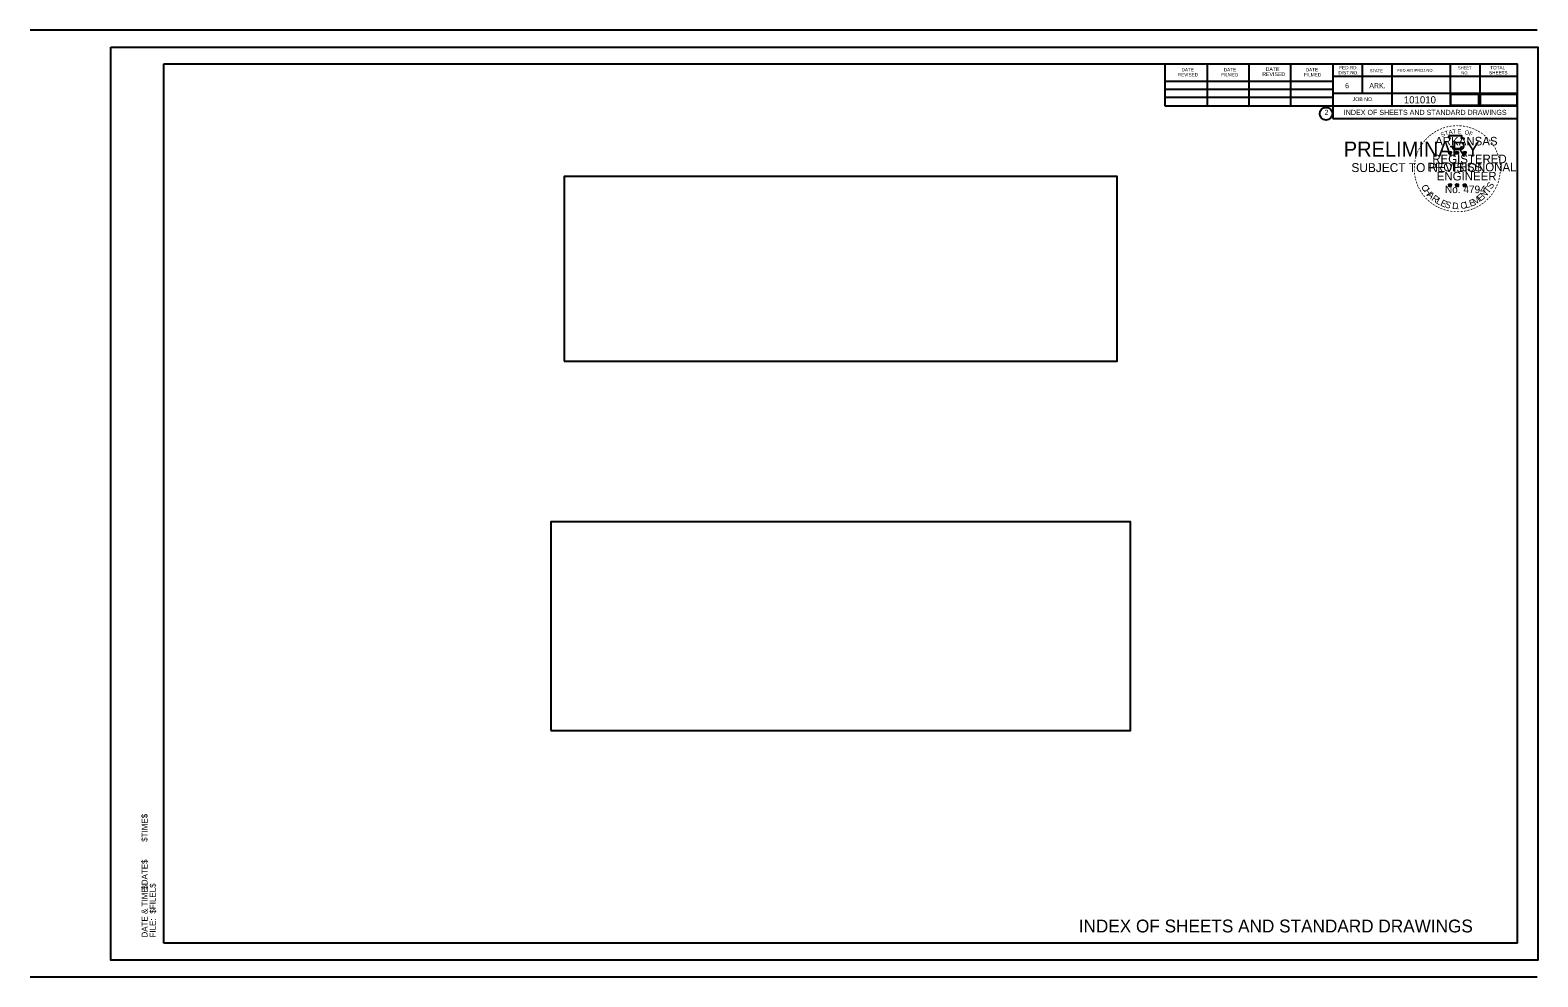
# Model space of a CAD drawing. Extents: x 3953 to 7490, y 10000 to 12548.
# Drawn here: x 3953 to 5714, y 10000 to 11106 of the extents above; entities that cross this region are included whole.
import ezdxf

# ---------------------------------------------------------------- set-up
doc = ezdxf.new("R2010")
doc.units = 0
for name, color, linetype in [('Default', 7, 'Continuous'), ('R_NoPlot', 7, 'Continuous'), ('STAMP_PE_FOSTER-SIGNATURE', 7, 'Continuous'), ('STAMP_PE_SEAL-INFO', 7, 'Continuous'), ('STAMP_PE_TAEGTMEYER', 7, 'Continuous'), ('STAMP_PRELIMINARY', 7, 'Continuous'), ('Total_Pages', 7, 'Continuous')]:
    doc.layers.add(name, color=color, linetype=linetype)

msp = doc.modelspace()

# ---------------------------------------------------------------- linework, layer by layer
at = {"layer": 'Default'}
for points in [[(5612.1, 11018.4), (5645.4, 11018.4), (5645.4, 11030.9), (5612.1, 11030.9)], [(4577.1, 10719.4), (5222.9, 10719.4), (5222.9, 10935.1), (4577.1, 10935.1)], [(4561.7, 10288), (5238.3, 10288), (5238.3, 10531.8), (4561.7, 10531.8)]]:
    msp.add_lwpolyline(points, close=True, dxfattribs=at)
at = {"layer": 'R_NoPlot'}
msp.add_lwpolyline([(4047.5, 11086.2), (5714.2, 11086.2), (5714.2, 10019.5), (4047.5, 10019.5)], close=True, dxfattribs=at)
at = {"layer": 'STAMP_PE_FOSTER-SIGNATURE'}
for p, q in [((5609.8, 10963.4), (5611.6, 10962.9)), ((5609.8, 10963.4), (5611.1, 10963.2)), ((5609.8, 10963.4), (5611, 10962.8)), ((5610.5, 10961.4), (5611.6, 10962.9)), ((5610.5, 10961.4), (5611.1, 10962.6)), ((5610.5, 10961.4), (5611.6, 10962.5)), ((5611.6, 10964.7), (5611.4, 10963.5)), ((5611.6, 10962.9), (5611.6, 10964.7)), ((5611.6, 10964.7), (5611.8, 10963.5)), ((5613.3, 10963.4), (5611.6, 10962.9)), ((5612.6, 10961.4), (5611.6, 10962.9)), ((5612.6, 10961.4), (5611.6, 10962.5)), ((5613.3, 10963.4), (5611.9, 10963.2)), ((5612.6, 10961.4), (5612, 10962.9)), ((5613.3, 10963.4), (5612.3, 10962.9)), ((5618.2, 10963.4), (5619.9, 10962.9)), ((5618.2, 10963.4), (5619.5, 10963.2)), ((5618.2, 10963.4), (5619.4, 10962.8)), ((5618.9, 10961.4), (5619.9, 10962.9)), ((5618.9, 10961.4), (5619.5, 10962.6)), ((5618.9, 10961.4), (5619.9, 10962.5)), ((5619.9, 10964.7), (5619.7, 10963.5)), ((5619.9, 10962.9), (5619.9, 10964.7)), ((5619.9, 10964.7), (5620.2, 10963.5)), ((5621.7, 10963.4), (5619.9, 10962.9)), ((5621, 10961.4), (5619.9, 10962.9)), ((5621, 10961.4), (5619.9, 10962.5)), ((5621.7, 10963.4), (5620.2, 10963.2)), ((5621, 10961.4), (5620.3, 10962.9)), ((5621.7, 10963.4), (5620.6, 10962.9)), ((5627, 10963.4), (5628.8, 10962.8)), ((5627, 10963.4), (5628.3, 10963.2)), ((5627, 10963.4), (5628.2, 10962.8)), ((5627.7, 10961.3), (5628.8, 10962.8)), ((5627.7, 10961.3), (5628.3, 10962.6)), ((5627.7, 10961.3), (5628.7, 10962.4)), ((5628.8, 10964.7), (5628.5, 10963.4)), ((5629.8, 10961.3), (5628.7, 10962.4)), ((5628.8, 10962.8), (5628.8, 10964.7)), ((5628.8, 10964.7), (5629, 10963.4)), ((5630.5, 10963.4), (5628.8, 10962.8)), ((5629.8, 10961.3), (5628.8, 10962.8)), ((5630.5, 10963.4), (5629.1, 10963.1)), ((5629.8, 10961.3), (5629.1, 10962.8)), ((5630.5, 10963.4), (5629.5, 10962.9)), ((5609.8, 10925.6), (5611.6, 10925)), ((5609.8, 10925.6), (5611.1, 10925.4)), ((5609.8, 10925.6), (5611, 10925)), ((5610.5, 10923.5), (5611.6, 10925)), ((5610.5, 10923.5), (5611.1, 10924.8)), ((5610.5, 10923.5), (5611.6, 10924.6)), ((5611.6, 10926.8), (5611.4, 10925.6)), ((5611.6, 10925), (5611.6, 10926.8)), ((5611.6, 10926.8), (5611.8, 10925.6)), ((5613.3, 10925.6), (5611.6, 10925)), ((5612.6, 10923.5), (5611.6, 10925)), ((5612.6, 10923.5), (5611.6, 10924.6)), ((5613.3, 10925.6), (5611.9, 10925.3)), ((5612.6, 10923.5), (5611.9, 10925)), ((5613.3, 10925.6), (5612.3, 10925.1)), ((5618.2, 10925.6), (5619.9, 10925)), ((5618.2, 10925.6), (5619.4, 10925.4)), ((5618.2, 10925.6), (5619.3, 10925)), ((5618.8, 10923.5), (5619.9, 10925)), ((5618.8, 10923.5), (5619.5, 10924.8)), ((5618.8, 10923.5), (5619.9, 10924.6)), ((5619.9, 10926.8), (5619.7, 10925.6)), ((5619.9, 10925), (5619.9, 10926.8)), ((5619.9, 10926.8), (5620.2, 10925.6)), ((5621.6, 10925.6), (5619.9, 10925)), ((5621, 10923.5), (5619.9, 10925)), ((5621, 10923.5), (5619.9, 10924.6)), ((5621.6, 10925.6), (5620.2, 10925.3)), ((5621, 10923.5), (5620.3, 10925)), ((5621.6, 10925.6), (5620.6, 10925.1)), ((5627, 10925.5), (5628.7, 10925)), ((5627, 10925.5), (5628.3, 10925.3)), ((5627, 10925.5), (5628.2, 10924.9)), ((5627.7, 10923.5), (5628.7, 10925)), ((5627.7, 10923.5), (5628.3, 10924.7)), ((5627.7, 10923.5), (5628.7, 10924.6)), ((5628.7, 10926.8), (5628.5, 10925.5)), ((5628.7, 10925), (5628.7, 10926.8)), ((5628.7, 10926.8), (5629, 10925.5)), ((5630.5, 10925.5), (5628.7, 10925)), ((5629.8, 10923.5), (5628.7, 10925)), ((5629.8, 10923.5), (5628.7, 10924.6)), ((5630.5, 10925.5), (5629, 10925.3)), ((5629.8, 10923.5), (5629.1, 10924.9)), ((5630.5, 10925.5), (5629.5, 10925))]:
    msp.add_line(p, q, dxfattribs=at)
for points in [[(5610, 10982.8), (5611.4, 10978.7)], [(5627.6, 10978.2), (5628.3, 10979.6), (5624.9, 10979.5), (5625.6, 10982.8), (5610, 10982.8)], [(5612.5, 10970.7), (5612.5, 10970.3), (5615.3, 10970.2), (5615, 10967.8), (5624.4, 10967.8), (5625.4, 10970.5)], [(5611.6, 10964.7), (5612.6, 10961.4), (5609.8, 10963.4), (5613.3, 10963.4), (5610.5, 10961.4), (5611.6, 10964.7)], [(5619.9, 10964.7), (5621, 10961.4), (5618.2, 10963.4), (5621.7, 10963.4), (5618.9, 10961.4), (5619.9, 10964.7)], [(5628.8, 10964.7), (5629.8, 10961.3), (5627, 10963.4), (5630.5, 10963.4), (5627.7, 10961.3), (5628.8, 10964.7)], [(5611.6, 10926.8), (5612.6, 10923.5), (5609.8, 10925.6), (5613.3, 10925.6), (5610.5, 10923.5), (5611.6, 10926.8)], [(5619.9, 10926.8), (5621, 10923.5), (5618.2, 10925.6), (5621.6, 10925.6), (5618.8, 10923.5), (5619.9, 10926.8)], [(5628.7, 10926.8), (5629.8, 10923.5), (5627, 10925.5), (5630.5, 10925.5), (5627.7, 10923.5), (5628.7, 10926.8)]]:
    msp.add_lwpolyline(points, dxfattribs=at)
for centre, radius in [((5611.6, 10962.9), 0.861), ((5611.6, 10962.9), 0.723), ((5611.6, 10962.9), 0.579), ((5611.6, 10962.9), 0.495), ((5611.6, 10962.9), 0.374), ((5611.6, 10962.9), 0.248), ((5611.6, 10962.9), 0.148), ((5619.9, 10962.9), 0.861), ((5619.9, 10962.9), 0.723), ((5619.9, 10962.9), 0.579), ((5619.9, 10962.9), 0.495), ((5619.9, 10962.9), 0.374), ((5619.9, 10962.9), 0.248), ((5619.9, 10962.9), 0.148), ((5628.7, 10962.8), 0.861), ((5628.7, 10962.8), 0.723), ((5628.7, 10962.8), 0.579), ((5628.7, 10962.8), 0.495), ((5628.7, 10962.8), 0.374), ((5628.7, 10962.8), 0.248), ((5628.7, 10962.8), 0.148), ((5611.6, 10925), 0.861), ((5611.6, 10925), 0.723), ((5611.6, 10925), 0.579), ((5611.6, 10925), 0.495), ((5611.6, 10925), 0.374), ((5611.6, 10925), 0.248), ((5611.6, 10925), 0.148), ((5619.9, 10925), 0.861), ((5619.9, 10925), 0.723), ((5619.9, 10925), 0.579), ((5619.9, 10925), 0.495), ((5619.9, 10925), 0.374), ((5619.9, 10925), 0.248), ((5619.9, 10925), 0.148), ((5628.7, 10925), 0.861), ((5628.7, 10925), 0.723), ((5628.7, 10925), 0.579), ((5628.7, 10925), 0.495), ((5628.7, 10925), 0.374), ((5628.7, 10925), 0.248), ((5628.7, 10925), 0.148)]:
    msp.add_circle(centre, radius, dxfattribs=at)
at = {"layer": 'STAMP_PRELIMINARY'}
for p, q in [((5713.4, 11106.1), (3953.4, 11106.1)), ((4109.5, 11066.7), (5690.4, 11066.7)), ((4109.5, 10039.4), (4109.5, 11066.7)), ((4872.1, 11065.4), (4872.1, 11065.4)), ((4872.1, 11065.4), (4872.1, 11065.4)), ((5279.1, 11017.3), (5279.1, 11066.7)), ((5328.4, 11017.3), (5328.4, 11065.7)), ((5377.2, 11017.3), (5377.2, 11065.7)), ((5425.6, 11017.3), (5425.6, 11065.7)), ((5474.9, 11066.7), (5474.9, 11002.7)), ((5509.1, 11066.7), (5509.1, 11032)), ((5543.8, 11066.7), (5543.8, 11017.3)), ((5611.7, 11066.7), (5611.7, 11017.3)), ((5646.4, 11066.7), (5646.4, 11017.3)), ((5690.4, 10039.4), (5690.4, 11066.7)), ((5279.1, 11046.6), (5474.9, 11046.6)), ((5690.4, 11052), (5474.9, 11052)), ((5690.4, 11052.1), (5690.4, 11052.1)), ((5279.1, 11037.3), (5474.9, 11037.3)), ((5279.1, 11027.6), (5474.9, 11027.6)), ((5690.4, 11032), (5474.9, 11032)), ((5690.4, 11017.3), (5279.1, 11017.3)), ((5474.9, 11002.7), (5690.4, 11002.7)), ((5690.4, 10039.4), (4109.5, 10039.4)), ((3953.4, 10000), (5713.4, 10000))]:
    msp.add_line(p, q, dxfattribs=at)
msp.add_circle((5466.9, 11008.4), 7.33, dxfattribs=at)
at = {"layer": 'Total_Pages'}
msp.add_lwpolyline([(5646.9, 11018.4), (5690, 11018.4), (5690, 11030.9), (5646.9, 11030.9)], close=True, dxfattribs=at)

# ---------------------------------------------------------------- texts
at = {"layer": 'Default'}
for s, height, p in [('$TIME$', 6.98, (4090.5, 10157.8)), ('$DATE$', 6.98, (4090.5, 10101.9)), ('$FILEL$', 6.98, (4100.1, 10073.9)), ('DATE & TIME:', 6.984, (4090.5, 10046)), ('FILE: ', 6.98, (4100.1, 10046))]:
    msp.add_text(s, height=height, rotation=90, dxfattribs=at).set_placement(p)
at = {"layer": 'STAMP_PE_FOSTER-SIGNATURE'}
for s, height, rotation, p in [('-', 8, 34.0636, (5594.5, 10983.7)), ('-', 8, 28.7918, (5597.4, 10985.5)), ('-', 8, 24.3072, (5600.6, 10987.1)), ('-', 8, 19.1761, (5603.8, 10988.5)), ('T', 5, 16.4036, (5606.4, 10982.9)), ('-', 8, 13.6302, (5607.5, 10989.7)), ('A', 5, 11.2132, (5610.5, 10984.1)), ('-', 8, 10.2193, (5610.9, 10990.5)), ('T', 5, 6.0228, (5614.8, 10985)), ('-', 8, 5.8968, (5614.6, 10991)), ('-', 8, 0.1862, (5618.4, 10991.4)), ('E', 5, 0.8323, (5620.3, 10985.5)), ('-', 8, 357.743, (5622, 10991.3)), ('-', 8, 352.1617, (5625.8, 10991)), ('O', 5, 350.4515, (5628.3, 10984.5)), ('-', 8, 347.2049, (5629.4, 10990.5)), ('F', 5, 340.0707, (5633.1, 10983.3)), ('-', 8, 342.3362, (5632.5, 10989.7)), ('-', 8, 337.8551, (5636.2, 10988.6)), ('-', 8, 334.1211, (5639.4, 10987.2)), ('-', 8, 329.6409, (5642.3, 10985.8)), ('-', 8, 58.0706, (5579.1, 10967.4)), ('-', 8, 54.2325, (5580.7, 10970.1)), ('-', 8, 50.6142, (5582.8, 10972.9)), ('-', 8, 48.4231, (5584.8, 10975.3)), ('-', 8, 42.9622, (5587, 10977.7)), ('-', 8, 38.9507, (5589.2, 10979.8)), ('-', 8, 36.2317, (5591.6, 10981.7)), ('S', 5, 21.594, (5601.8, 10981.2)), ('-', 8, 325.8627, (5645.5, 10984)), ('-', 8, 320.5297, (5648.5, 10981.9)), ('-', 8, 315.5786, (5651.5, 10979.4)), ('-', 8, 309.8797, (5654.4, 10976.7)), ('-', 8, 306.6522, (5657, 10973.7)), ('-', 7, 303.6753, (5659.4, 10970.8)), ('-', 8, 81.2013, (5573.5, 10951)), ('-', 8, 75.461, (5574.1, 10954.6)), ('-', 8, 72.3945, (5575.1, 10958.2)), ('-', 8, 67.7743, (5576.2, 10961.3)), ('-', 8, 62.8713, (5577.5, 10964.4)), ('-', 8, 299.6684, (5661, 10967.8)), ('-', 8, 294.6628, (5662.6, 10964.7)), ('-', 8, 290.5728, (5663.9, 10961.9)), ('-', 8, 285.1233, (5665.1, 10959)), ('-', 8, 280.5493, (5666.1, 10955.3)), ('-', 8, 89.0622, (5573, 10944.1)), ('-', 8, 94.1959, (5573.2, 10940.5)), ('-', 8, 98.9479, (5573.5, 10937.1)), ('-', 8, 85.1863, (5573.1, 10947.6)), ('-', 8, 101.7149, (5574.2, 10933.5)), ('-', 8, 260.9953, (5666.9, 10938)), ('-', 8, 263.5172, (5667.3, 10941.3)), ('-', 8, 276.5962, (5666.9, 10951.4)), ('-', 8, 274.3301, (5667.2, 10947.8)), ('-', 8, 269.9407, (5667.4, 10944.6)), ('-', 8, 105.4578, (5575, 10930.5)), ('-', 8, 109.0874, (5576.1, 10927.3)), ('-', 8, 114.0643, (5577.3, 10924.3)), ('-', 8, 115.7289, (5578.9, 10921.3)), ('-', 8, 120.4471, (5580.7, 10918.3)), ('C', 7.7, 296.9133, (5577.7, 10923.3)), ('H', 7.7, 303.2799, (5580.7, 10918.1)), ('N', 7.7, 45.1449, (5651.6, 10909.3)), ('T', 7.7, 51.5114, (5656.4, 10914.5)), ('S', 7.7, 57.878, (5660, 10919.7)), ('-', 8, 239.0712, (5661.1, 10920.8)), ('-', 8, 244.6197, (5663, 10924.5)), ('-', 8, 247.8887, (5664.3, 10927.7)), ('-', 8, 255.7626, (5665.4, 10931.2)), ('-', 8, 255.7626, (5666.4, 10934.7)), ('-', 8, 125.8934, (5582.7, 10915.5)), ('-', 8, 130.7181, (5585, 10912.8)), ('-', 8, 134.2238, (5587.6, 10910)), ('A', 7.7, 316.013, (5584.3, 10913)), ('-', 8, 138.9338, (5590.2, 10907.7)), ('-', 8, 144.6463, (5593, 10905.7)), ('R', 7.7, 322.3796, (5589.4, 10908.1)), ('-', 8, 148.0898, (5595.8, 10903.8)), ('-', 8, 151.5704, (5598.7, 10902.2)), ('L', 7.7, 328.7461, (5594.6, 10904.3)), ('-', 8, 154.6002, (5601.3, 10901)), ('E', 7.7, 335.1127, (5599.6, 10901.5)), ('S', 7.7, 341.4792, (5604.9, 10899.4)), ('D', 7.7, 354.2124, (5613.8, 10897.3)), ('C', 7.7, 6.9455, (5624.2, 10897.1)), ('L', 7.7, 13.3121, (5630.1, 10898.1)), ('E', 7.7, 19.6786, (5635.6, 10899.7)), ('M', 7.7, 32.4117, (5640.7, 10901.5)), ('-', 8, 207.3568, (5643.7, 10903.3)), ('E', 7.7, 38.7783, (5647.1, 10905.6)), ('-', 8, 212.2491, (5646.5, 10905)), ('-', 8, 215.7363, (5649.2, 10907)), ('-', 8, 221.0851, (5651.9, 10909.3)), ('-', 8, 225.7653, (5654.5, 10911.9)), ('-', 8, 231.2538, (5656.9, 10914.7)), ('-', 8, 233.8452, (5659.1, 10917.5)), ('-', 8, 158.5612, (5604.4, 10899.7)), ('-', 8, 162.7983, (5607.8, 10898.6)), ('-', 8, 167.5555, (5611.4, 10897.8)), ('-', 8, 173.1155, (5615.3, 10897.3)), ('-', 8, 176.5183, (5619, 10897)), ('-', 8, 181.5918, (5622.7, 10897.1)), ('.', 7.7, 0.5789, (5619.6, 10896.9)), ('-', 8, 185.8167, (5626.8, 10897.5)), ('-', 8, 191.2858, (5630.5, 10898.1)), ('-', 8, 195.4743, (5634.1, 10899.1)), ('-', 8, 200.7184, (5637.5, 10900.3)), ('-', 8, 204.2516, (5640.6, 10901.7))]:
    msp.add_text(s, height=height, rotation=rotation, dxfattribs=at).set_placement(p)
for s, height, p in [('ARKANSAS', 10, (5594.3, 10971.4)), ('REGISTERED', 10, (5590.9, 10950.6)), ('PROFESSIONAL', 10, (5585.2, 10941.1)), ('ENGINEER', 10, (5596.1, 10930.5)), ('No. 4794', 8.78, (5605.7, 10915.7))]:
    msp.add_text(s, height=height, dxfattribs=at).set_placement(p)
at = {"layer": 'STAMP_PE_SEAL-INFO'}
for s, height, p in [('PRELIMINARY', 17.5, (5487.5, 10958.4)), ('SUBJECT TO REVISION', 10.376, (5496.5, 10940.3))]:
    msp.add_text(s, height=height, dxfattribs=at).set_placement(p)
at = {"layer": 'STAMP_PE_TAEGTMEYER'}
for s, height, p in [('101010', 8.4, (5557.7, 11020.5)), ('INDEX OF SHEETS AND STANDARD DRAWINGS', 6, (5487.6, 11007))]:
    msp.add_text(s, height=height, dxfattribs=at).set_placement(p)
at = {"layer": 'STAMP_PRELIMINARY'}
for s, height, p in [('DATE', 3.91, (5298.1, 11057.9)), ('DATE', 3.91, (5347.4, 11057.9)), ('DATE', 4.4, (5396.3, 11058.4)), ('DATE', 3.91, (5443.2, 11057.9)), ('DIST.NO.', 3.91, (5481.3, 11054.4)), ('FED.RD.', 3.91, (5482.3, 11060.3)), ('STATE', 3.42, (5517.9, 11056.9)), ('FED.AID PROJ.NO.', 3.42, (5550.2, 11057.4)), ('SHEET', 3.42, (5621, 11060.3)), ('NO.', 3.42, (5624.9, 11054.4)), ('SHEETS', 3.91, (5657.2, 11054.4)), ('TOTAL', 3.91, (5658.6, 11060.3)), ('REVISED', 3.91, (5293.7, 11052)), ('FILMED', 3.91, (5344.5, 11052)), ('REVISED', 4.4, (5392.4, 11052.5)), ('FILMED', 3.91, (5441.2, 11052)), ('6', 5.86, (5489.1, 11038.3)), ('ARK.', 5.86, (5517.4, 11038.3)), ('JOB NO.', 4.4, (5497.9, 11023.2)), ('2', 5.86, (5465.2, 11007.1)), ('INDEX OF SHEETS AND STANDARD DRAWINGS', 15, (5178, 10051.9))]:
    msp.add_text(s, height=height, dxfattribs=at).set_placement(p)

doc.saveas('drawing.dxf')
